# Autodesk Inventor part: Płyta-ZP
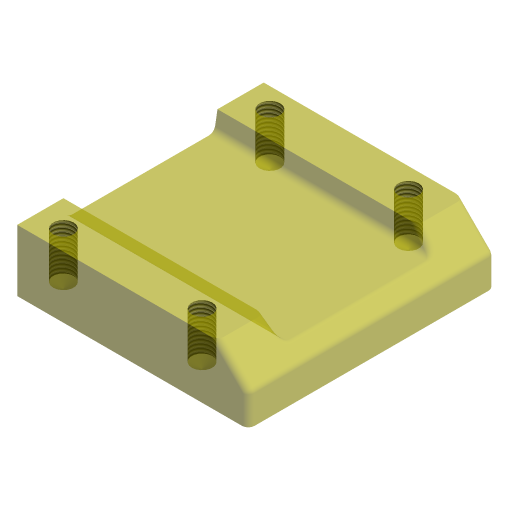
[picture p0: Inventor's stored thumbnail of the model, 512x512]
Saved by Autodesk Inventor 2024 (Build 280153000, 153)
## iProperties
Company: ATC
Shininess: 0.0
Length Units: 11269
Angle Units: 11279
Time Units: 11290
Mass Units: 11283
Length Display Precision: 3
Angle Display Precision: 2
Compacted: True
Created: 2023-03
Part Number: Płyta-ZP
Document SubType Name: Modeling
Designer: Andrzej Jaskulski
Density: 1 g/cm^3
Material: Default
Appearance: Yellow(Clear)
Checked By: A.J.
Engr Approved By: Andrzej Jaskulski
Mfg Approved By: Andrzej Jaskulski
Authority: A.J.
Density: 0.0
Volumn: 0.0
Area: 0.0
PropertySet Name: Model Information
Control State: 0
Master: False
Checked Out: False
Title: A.J.: Kurs R2024-MEP
Author: Andrzej Jaskulski
Revision Number: 1/24
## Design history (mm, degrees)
node "Sketch1"
node "Extrusion1" dims "d0" = 0, "d1" = 20
  sketch "Sketch2"
    geometry: L1 (-60, 0)-(20, 0); L2 (20, 0)-(20, 75) reference; L3 (20, 75)-(-60, 75) reference; L4 (-60, 75)-(-60, 0)
    constraints: 8 end point, 2 parallel, 1 horizontal, 1 perpendicular, 1 vertical
    dimensions: "d3" = 80 distance of L1.start L1.end (= ROZSTAW); "d2" = 75 distance of L1.end L2.end
node "Chamfer1" dims "d4" = 10, "d5" = 10, "d29" = 45 deg
node "Extrusion2" dims "d6" = 0, "d7" = 10
  sketch "Sketch3"
    geometry: L1 (0, -20)-(80, -20) reference; L2 (80, 0)-(0, 0) reference; L3 (15, -20)-(16.058, -14); L4 (16.058, -14)-(63.942, -14); L5 (63.942, -14)-(65, -20); L6 (40, -14)-(40, -20)
    constraints: 8 end point, 2 midpoint, 2 point on line, 1 equal length, 1 parallel, 1 vertical
    dimensions: "d9" = 6 distance between parallel lines of L1 L4; "d8" = 100 deg angle of L4 L3; "d10" = 15 distance of L3.start L1.start; "d23" = 15 distance of L5.end L1.end
node "Fillet1" dims "d11" = 2, "d12" = 2
node "Hole1" dims "d17" = 118 deg, "d18" = 60 deg, "d19" = 2, "d20" = 4, "d21" = 15, "d22" = 6.64, "d28" = 6
  sketch "Sketch4"
    geometry: L1 (-53.5, 66.5)-(13.5, 66.5); L2 (13.5, 66.5)-(13.5, 21.5); L3 (13.5, 21.5)-(-53.5, 21.5); L4 (-53.5, 21.5)-(-53.5, 66.5); L5 (-42.264, 75)-(2.264, 75) reference; L6 (20, 75)-(20, 12.828) reference
    constraints: 8 end point, 2 parallel, 1 horizontal, 1 perpendicular
    dimensions: "d15" = 8.5 distance between parallel lines of L5 L1 (= odstęp2); "d14" = 6.5 distance between parallel lines of L2 L6 (= d26); "d16" = 67 distance of L1.start L1.end (= ROZSTAW - 2 x odstęp); "d13" = 45 distance between parallel lines of L3 L1 (= d25)
node "Bryła1"
node "Korpusy bryłowe"
node "Korpusy powierzchniowe"
other parameters: "d25" = 45, "d26" = 6.5, "d27" = 8.5, "odstęp" = 6.5 [user parameter; used in 1 equation term], "ROZSTAW" = 80 [user parameter; used in 2 equation terms], "odstęp2" = 8.5 [user parameter; used in 1 equation term]
